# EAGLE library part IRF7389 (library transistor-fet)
Complimentary Half Bridge HEXFET Power MOSFET Source: http://www.irf.com/product-info/datasheets/data/irf7389.pdf
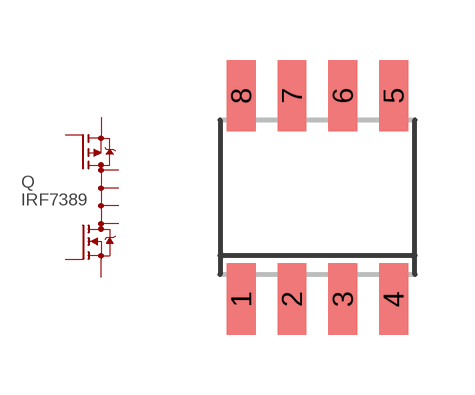
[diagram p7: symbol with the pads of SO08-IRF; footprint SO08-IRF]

Designator prefix Q

## IRF7389  [SO08-IRF]
1  N-S  pas
2  N-G  pas
3  P-S  pas
4  P-G  pas
5  D  pas
6  D  pas
7  D  pas
8  D  pas

## Footprint SO08-IRF (pad centres in mm)
SO8 Source: http://www.irf.com/product-info/datasheets/data/irf7389.pdf
smd 0.72 x 1.78: 1 -1.905,-2.543; 2 -0.635,-2.543; 3 0.635,-2.543; 4 1.905,-2.543; 5 1.905,2.543; 6 0.635,2.543; 7 -0.635,2.543; 8 -1.905,2.543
